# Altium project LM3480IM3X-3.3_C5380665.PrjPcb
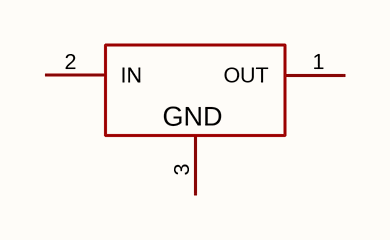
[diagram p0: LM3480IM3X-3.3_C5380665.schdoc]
1 sheet, 1 parts. Net scope: global (net labels, ports and power ports of the same name join across sheets).

## Sheet LM3480IM3X-3.3_C5380665.schdoc
size 127 x 101 mm

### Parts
U?  lm3480im3x-3.3_c5380665  [SOT-23-3_L2.9-W1.4-0.95-LS2.5-BR]  (value not drawn)

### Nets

Not connected (* = marked no-connect by the designer): U? 1(OUT) 2(IN) 3(GND)

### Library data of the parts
U? = lm3480im3x-3.3_c5380665: 输出极性:正极;工作电压:20V;输出电压:3.3V;输出电流:100mA;电源纹波抑制比(PSRR):49dB@(120Hz);输出类型:固定;; Manufacturer: TECH PUBLIC(台舟); AddInBom: yes; ModelId: 1594fcb3710a47cd9c2104225e74d8d7; ModelTransform: 114.173,100,0,90,0,0,0,0,0; Output Configuration: 正极; Voltage - Supply: 20V; Output Voltage: 3.3V; Output Current: 100mA; Voltage Dropout: 2V@(100mA); standby current: 3mA; Noise: 40uV; Output Type: 固定; Number of Outputs: 1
